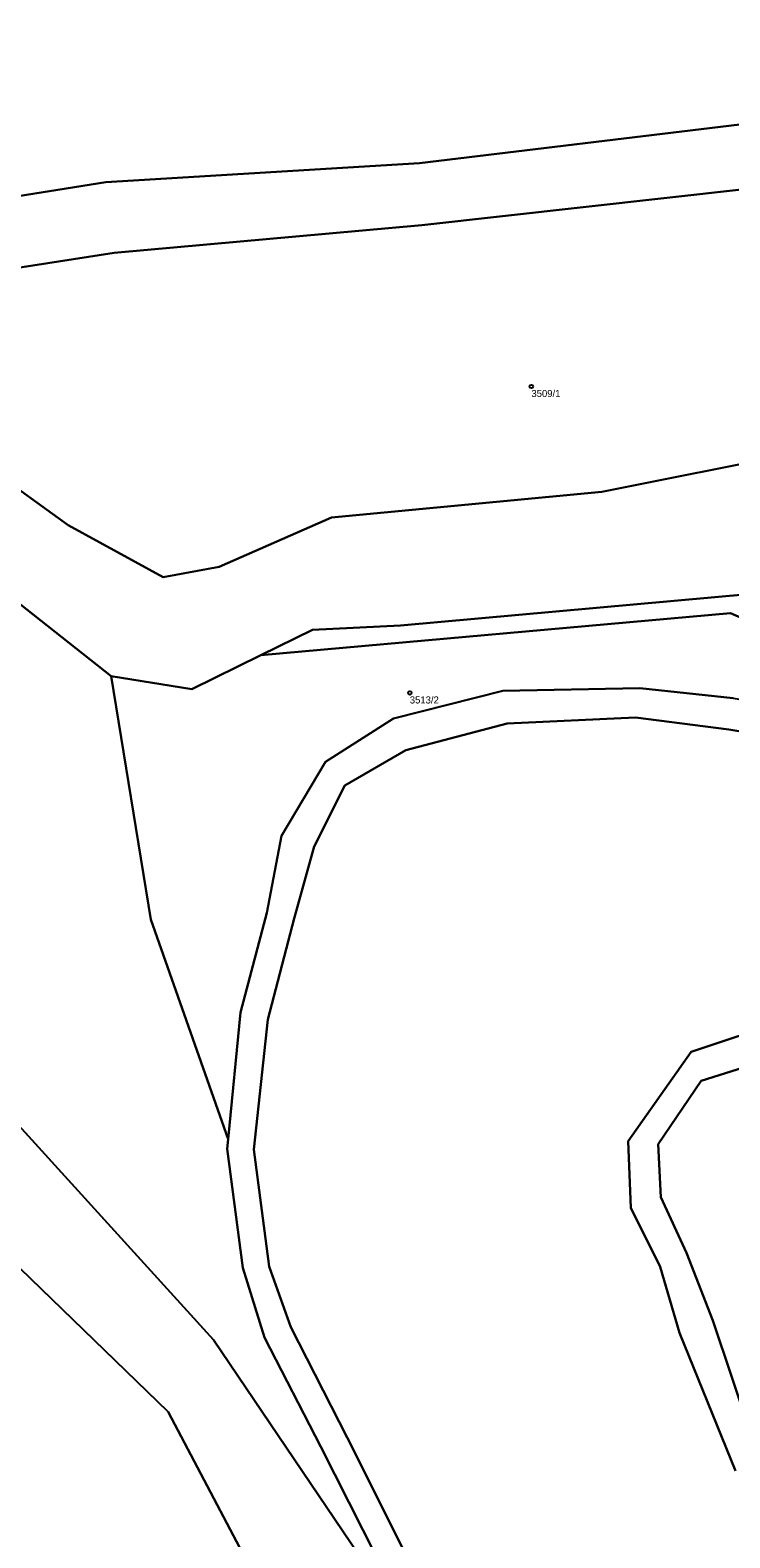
# Model space of a CAD drawing. Extents: x -878211 to -870363, y -1058464 to -1052522.
# Drawn here: x -876543.1 to -876444.5, y -1055057.5 to -1054845.1 of the extents above; entities that cross this region are included whole.
import ezdxf

# ---------------------------------------------------------------- set-up
doc = ezdxf.new("R2010")
doc.units = 0
doc.layers.add('Definiční body', color=7, linetype='Continuous')
doc.layers.add('Polygon parcely', color=7, linetype='Continuous')

msp = doc.modelspace()

# ---------------------------------------------------------------- linework, layer by layer
at = {"layer": 'Definiční body'}
for centre in [(-876472.48, -1054895.27994), (-876489.61, -1054938.44994)]:
    msp.add_circle(centre, 0.25, dxfattribs=at)
at = {"layer": 'Polygon parcely'}
for points in [[(-876563.05, -1054871.37), (-876532.44, -1054866.5), (-876488.24, -1054863.82), (-876443.11, -1054858.35), (-876365.9, -1054850.47), (-876313.89, -1054845.08), (-876301, -1054846.39), (-876227.86, -1054861.19)], [(-876559.92, -1054880.92), (-876531.23, -1054876.43), (-876487.93, -1054872.57), (-876442.47, -1054867.46), (-876365.19, -1054858.8), (-876318.87, -1054855.28), (-876302.34, -1054855.7), (-876221.35, -1054871.07), (-876224.9, -1054864.37), (-876227.86, -1054861.19), (-876301, -1054846.39), (-876313.89, -1054845.08), (-876365.9, -1054850.47), (-876443.11, -1054858.35), (-876488.24, -1054863.82)], [(-876212.02, -1054889.19), (-876283, -1054897.41), (-876292.85, -1054862.9), (-876318.87, -1054855.28), (-876344.84, -1054864.01), (-876366.82, -1054877.99), (-876391.52, -1054888.7), (-876408.62, -1054891.36), (-876419.53, -1054893.75), (-876428.36, -1054901.24), (-876431.43, -1054903.3), (-876435.27, -1054904.66), (-876462.57, -1054910.11), (-876500.65, -1054913.72), (-876516.44, -1054920.67), (-876524.33, -1054922.13), (-876537.71, -1054914.81), (-876553.21, -1054903.63)], [(-876488.24, -1054863.82), (-876532.44, -1054866.5), (-876563.05, -1054871.37)], [(-876554.58, -1054918.01), (-876531.66, -1054936.08), (-876520.3, -1054937.9), (-876510.58, -1054933.13), (-876503.33, -1054929.57), (-876490.9, -1054928.94), (-876441.45, -1054924.49), (-876428.71, -1054917.43), (-876427.47, -1054915.93), (-876423.48, -1054914.13), (-876418.87, -1054910.9), (-876408.73, -1054905.38), (-876399.9, -1054901.85), (-876380.69, -1054897.58), (-876356, -1054887.75), (-876339.28, -1054874.2), (-876318.21, -1054867.84), (-876309.04, -1054869.25), (-876299.88, -1054875.09), (-876297.96, -1054890.06), (-876291.78, -1054906.9), (-876262.86, -1054909.66), (-876243.34, -1054905.33)], [(-876444.08, -1054939.2), (-876457.23, -1054937.79), (-876476.52, -1054938.14), (-876491.88, -1054942.07), (-876501.47, -1054948.15), (-876507.69, -1054958.58), (-876509.73, -1054969.43), (-876513.45, -1054983.48), (-876515.19, -1055001.33), (-876515.32, -1055002.69), (-876513.13, -1055019.45), (-876510.07, -1055029.26), (-876502.13, -1055044.68), (-876494.27, -1055060.24)], [(-876490.62, -1055058.91), (-876498.45, -1055043.34), (-876506.36, -1055027.79), (-876509.41, -1055019.25), (-876511.56, -1055002.76), (-876509.6, -1054984.46), (-876505.88, -1054970.21), (-876503.08, -1054960.08), (-876498.77, -1054951.51), (-876490.17, -1054946.5), (-876475.88, -1054942.77), (-876457.82, -1054941.91), (-876444.66, -1054943.59), (-876415.24, -1054948.5)], [(-876415.24, -1054948.5), (-876444.66, -1054943.59), (-876457.82, -1054941.91), (-876475.88, -1054942.77), (-876490.17, -1054946.5), (-876498.77, -1054951.51), (-876503.08, -1054960.08), (-876505.88, -1054970.21), (-876509.6, -1054984.46), (-876511.56, -1055002.76), (-876509.41, -1055019.25), (-876506.36, -1055027.79), (-876498.45, -1055043.34), (-876490.62, -1055058.91)], [(-876557.59, -1055264.34), (-876528.13, -1055234.23), (-876525.04, -1055230.88), (-876518.66, -1055219.24), (-876512.88, -1055195.87), (-876514.81, -1055162.43), (-876498.93, -1055149.14), (-876495.27, -1055132.83), (-876492.3, -1055103.17), (-876496.77, -1055059.89), (-876517.27, -1055029.59), (-876567.56, -1054974.25)], [(-876436.53, -1054984.57), (-876449.98, -1054989), (-876458.84, -1055001.62), (-876458.46, -1055010.99), (-876454.33, -1055019.32), (-876451.62, -1055028.58), (-876443.73, -1055048.04)], [(-876443.73, -1055048.04), (-876451.62, -1055028.58), (-876454.33, -1055019.32), (-876458.46, -1055010.99), (-876458.84, -1055001.62), (-876449.98, -1054989), (-876436.53, -1054984.57)], [(-876441.73, -1055042.41), (-876446.93, -1055026.87), (-876450.62, -1055017.35), (-876454.27, -1055009.5), (-876454.62, -1055002), (-876448.56, -1054993.12), (-876436.65, -1054989.35)], [(-876436.65, -1054989.35), (-876448.56, -1054993.12), (-876454.62, -1055002), (-876454.27, -1055009.5), (-876450.62, -1055017.35), (-876446.93, -1055026.87), (-876441.73, -1055042.41)], [(-876574.39, -1054990.6), (-876523.64, -1055039.73), (-876508.95, -1055067.64), (-876504.73, -1055106.19), (-876506.17, -1055125.93), (-876506.27, -1055134.7), (-876514.06, -1055145.1), (-876522.43, -1055147.13), (-876526.61, -1055152.98), (-876528.02, -1055158.53), (-876529.36, -1055163.79), (-876527.01, -1055180.55), (-876525.65, -1055198.72), (-876532.38, -1055222.79), (-876551.19, -1055239.29)]]:
    msp.add_lwpolyline(points, dxfattribs=at)
for points in [[(-876563.1, -1054903.72), (-876553.21, -1054903.63), (-876537.71, -1054914.81), (-876524.33, -1054922.13), (-876516.44, -1054920.67), (-876500.65, -1054913.72), (-876462.57, -1054910.11), (-876435.27, -1054904.66), (-876431.43, -1054903.3), (-876428.36, -1054901.24), (-876419.53, -1054893.75), (-876408.62, -1054891.36), (-876391.52, -1054888.7), (-876366.82, -1054877.99), (-876344.84, -1054864.01), (-876318.87, -1054855.28), (-876365.19, -1054858.8), (-876442.47, -1054867.46), (-876487.93, -1054872.57), (-876531.23, -1054876.43), (-876559.92, -1054880.92), (-876580.14, -1054889.55), (-876591.08, -1054896.42), (-876570.94, -1054909.02)], [(-876515.19, -1055001.33), (-876526.09, -1054970.36), (-876531.66, -1054936.08), (-876554.58, -1054918.01), (-876565.02, -1054921.33), (-876573.4, -1054954.2), (-876567.56, -1054974.25), (-876517.27, -1055029.59), (-876496.77, -1055059.89), (-876492.3, -1055103.17), (-876495.27, -1055132.83), (-876481.01, -1055097.99), (-876482.74, -1055093.81), (-876488.9, -1055076.02), (-876494.27, -1055060.24), (-876502.13, -1055044.68), (-876510.07, -1055029.26), (-876513.13, -1055019.45), (-876515.32, -1055002.69)], [(-876392.93, -1054937.94), (-876405.43, -1054940.12), (-876441.45, -1054924.49), (-876490.9, -1054928.94), (-876503.33, -1054929.57), (-876510.58, -1054933.13), (-876444.45, -1054927.2), (-876418.9, -1054938.34), (-876398.61, -1054942.65), (-876345.83, -1054945.71), (-876345.46, -1054942.49)], [(-876501.47, -1054948.15), (-876491.88, -1054942.07), (-876476.52, -1054938.14), (-876457.23, -1054937.79), (-876444.08, -1054939.2), (-876414.59, -1054944.25), (-876398.52, -1054944.88), (-876373.73, -1054947.48), (-876346.55, -1054951.9), (-876345.83, -1054945.71), (-876398.61, -1054942.65), (-876418.9, -1054938.34), (-876444.45, -1054927.2), (-876510.58, -1054933.13), (-876520.3, -1054937.9), (-876531.66, -1054936.08), (-876526.09, -1054970.36), (-876515.19, -1055001.33), (-876513.45, -1054983.48), (-876509.73, -1054969.43), (-876507.69, -1054958.58)], [(-876582.2, -1055078.08), (-876561.62, -1055117.7), (-876557.94, -1055161.88), (-876528.02, -1055158.53), (-876526.61, -1055152.98), (-876522.43, -1055147.13), (-876514.06, -1055145.1), (-876506.27, -1055134.7), (-876506.17, -1055125.93), (-876504.73, -1055106.19), (-876508.95, -1055067.64), (-876523.64, -1055039.73), (-876574.39, -1054990.6), (-876576.93, -1054984.33), (-876602.47, -1054993.7)]]:
    msp.add_lwpolyline(points, close=True, dxfattribs=at)

# ---------------------------------------------------------------- texts
at = {"layer": 'Definiční body'}
for s, p in [('3509/1', (-876472.48, -1054896.769)), ('3513/2', (-876489.61, -1054939.939))]:
    msp.add_text(s, height=0.999996, dxfattribs=at).set_placement(p)

doc.saveas('drawing.dxf')
